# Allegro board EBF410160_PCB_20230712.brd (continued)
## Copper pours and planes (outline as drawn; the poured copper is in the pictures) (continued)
N18173560 on BOTTOM: 22.35,88.9 22.35,83.44 22.73,83.06 23.37,83.06 23.62,83.31 23.62,87.12 23.75,87.25 27.05,87.25 27.05,88.01 23.75,88.01 23.62,88.14 23.62,89.15 23.5,89.28 22.73,89.28

Small or netless copper shapes (teardrops, artwork), in the pictures only: 30 on TOP, 48 on BOTTOM

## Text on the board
Ref Des/Silkscreen Bottom: T1 | GND | R1 | T2 | EBF410160 | 20230712 | R2 | 2A | 2B | 1A | 1B | 3V3 | INT | RES | SCL | SDA | SCL0 | SDA0 | SCL1 | SDA1 | TXD0 | RXD0 | TXD1 | RXD1 | SIM CARD | TF CARD | MIPI CSI RX0 | MIPI CSI RX1
User.Comments: CR_DCDC2_2
Ref Des/Silkscreen Top: 12V | GND | 3V3 | 5V | DC-12V | RTC | RS232 | FAN | TYPE-C OTG | SPK | EAR | RS485 | MIC | HDMI2.0 PORT | ETH | I2C0 | SPI_D0 | USB3.0 HOST/OTG | I2C1 | UART0 | USB2.0 HOST | UART1 | IR_REC | SARADC | POWERON | RESET | RECOVERY | RXD | TXD | NC | INP | INN | EDP TOUCH | MIPI_DSI_TX1 | EDP DSI | LVDS TX0 | EBF410160 | 20230712 | + | -
COMPVAL_TYPE_BOTTOM: B | 12V | GND | 3V3 | 5V | 6 | A | T1_232 | 259 | DC-12V | RTC | R1_232 | T2_232 | FAN | USB_OTG | R2_232 | SPK | 4 | 485_2A | EAR | 485_2B | 145 | 485_1A | 143 | 485_1B | MIC | HDMI | 1 | 2 | 10 | C | USB3.0/USB2.0 HOST | 20 | 30 | USB2.0 HOST | 40 | 39 | IR_REC | D | C60 | Z4 | J3 | F1 | J6 | J1 | D1 | C2 | C3 | J7 | C1 | J2 | C189 | C190 | J29 | C185 | C186 | R216 | C188 | Z7 | R220 | Z10 | J11 | R74 | C131 | R73 | D29 | D28 | D30 | D31 | Q11 | Q10 | Q9 | J30 | R162 | R169 | R170 | R166 | R176 | R173 | R188 | J24 | C109 | R127 | R128 | Q7 | R126 | R125 | D36 | D35 | C107 | C108 | U17 | CN1 | C153 | R187 | R199 | R198 | C150 | R180 | C139 | R165 | R171 | U31 | C165 | R196 | R192 | C157 | C156 | R189 | Y2 | C167 | J18 | J19 | J22 | SARADC | PWRON | RESET | RECOVERY | RXD | TXD | NC | 260 | J12 | 146 | 144 | EDP TOUCH | ETH0 | MIPI_DSI_TX0 | MIPI_DSI_TX1 | EDP DSI | Z1 | R23 | SW4 | SW1 | SW2 | SW3 | C61 | R25 | C37 | R24 | J8 | R16 | LED4 | J16 | L8 | J25 | R215 | J27 | J26 | U27 | U28 | U26 | D27 | R190 | R191 | J14 | J10 | J23 | R160 | R158 | C144 | C137 | C154 | C145 | C138 | C155 | J15 | C180 | C179 | C184 | C110 | C111 | R214 | R213 | J17 | C106 | C181 | R212 | R211 | C183 | R194 | Q13 | LED3 | J13 | U29 | U33 | U32 | C136 | U30 | U34 | Q12 | LED2 | R146 | R49 | C119 | R145 | R48 | Q14 | C166 | R45 | R142 | C120 | U22 | R143 | U11 | LED1
DEVICE_TYPE_TOP: F | E | SPI_D0 | GND | C33 | C7 | L1 | R2 | R34 | R32 | R41 | Z3 | Z2 | R40 | U12 | R6 | R4 | C8 | C15 | Q3 | C21 | C22 | C23 | L3 | D7 | C67 | C19 | C36 | C35 | C34 | R26 | R33 | C41 | R31 | R13 | R11 | C20 | R1 | C4 | U25 | C126 | C125 | R153 | C124 | R150 | C58 | R38 | U2 | R12 | C10 | C11 | D2 | C38 | R27 | R30 | R29 | C51 | C50 | C26 | C25 | C24 | Q1 | Z8 | D34 | R138 | C31 | C32 | C13 | C12 | C14 | C30 | Z9 | U8 | D33 | Z11 | J5 | Z13 | C55 | U13 | D24 | Z6 | R218 | C187 | D22 | U15 | C86 | D25 | D23 | C91 | L6 | Y1 | D21 | R119 | R120 | D32 | R107 | R106 | U14 | R100 | R102 | R101 | R154 | R155 | R99 | R97 | R96 | U35 | R104 | R103 | R105 | R94 | R93 | R95 | R159 | C103 | C104 | R90 | R91 | C80 | C79 | R92 | R89 | R157 | L7 | R156 | L5 | C85 | U18 | R136 | U19 | C182 | U36 | R148 | U24 | C54 | L10 | R66 | R65 | R64 | R63 | C73 | R62 | R61 | R60 | D18 | D17 | D16 | D15 | C74 | D14 | D13 | D12 | C175 | C173 | C174 | U20 | R201 | C178 | C116 | R144 | U38 | R172 | C130 | U21 | R46 | C129 | C127 | J9 | U37 | R167 | R161 | C118 | R141 | R47 | C66 | C65 | J21 | J20 | 3V3 | INT | RST | SCL | SDA | SIM CARD | TF CARD | MIPI CSI RX0 | MIPI CSI RX1 | 24 | U3 | R42 | U5 | C62 | C6 | C40 | C49 | C43 | U9 | C5 | U10 | R19 | C39 | C48 | C42 | R22 | C28 | R20 | R39 | C29 | C59 | R21 | L2 | R50 | R59 | U4 | U7 | U6 | U1 | Q5 | D11 | R51 | D6 | C47 | C52 | C9 | C57 | R3 | R5 | R58 | Q2 | D9 | R18 | Q4 | Q6 | R17 | R57 | R10 | D10 | R135 | R9 | R223 | R56 | D26 | R134 | D8 | R52 | R224 | R37 | R53 | R55 | C70 | C191 | R54 | R217 | C72 | C71 | C68 | C69 | R82 | R81 | R219 | D20 | R68 | R72 | R78 | R77 | C76 | R70 | C94 | R221 | R80 | U16 | C92 | R79 | R98 | C83 | R108 | D19 | R109 | C84 | L9 | R67 | R71 | R76 | R75 | C75 | R69 | C77 | R195 | C162 | L4 | R193 | C78 | C163 | R114 | C164 | R111 | R117 | R116 | R118 | C105 | R110 | R112 | R124 | C102 | R123 | C98 | C82 | C87 | C81 | C90 | R130 | R131 | R137 | R84 | C171 | C114 | R85 | C170 | C115 | R83 | C172 | C123 | R86 | R205 | C122 | R203 | C169 | R206 | C168 | R87 | R88 | C121 | R147 | R140 | R139 | R204 | R133 | R200 | R132 | C176 | C113 | R202 | C112 | R210 | C177 | C117 | R209 | R208 | R186 | C64 | R185 | R184 | R44 | R183 | R181 | R179 | R178 | R177 | R152 | C128 | 20230523 | EBF410090
DEVICE_TYPE_BOTTOM: MASKROM | SS3 | SS1 | C4 | C2 | SS4 | SS2 | J6 | J5 | J9
BODY_CENTER: 2 | 80 | 79 | R1 | C6 | C1 | J3 | J1 | J4 | J2 | C3
DIMENSION: Unit:mm | X4
User.9: FIGURE | SIZE | 12.0 | 19.685 | 21.654 | 25.591 | 27.559 | 33.465 | 35.43 | 39.37 | 47.244 | 72.047 | 78.74 | 125.98 | 166.142 | 23.622 | 25.59 | 35.433 | 40.0 | 43.307 | 62.992 | 78.701 | 125.984 | 127.953 | 47.24x23.62 | 66.902x19.701 | 66.93x23.62 | 70.902x15.701 | 78.74x39.37 | 94.488x94.488 | 106.299x35.429 | DRILL CHART: TOP to BOTTOM | ALL UNITS ARE IN MILS | PLATED | NON-PLATED | QTY | 1177 | 2 | 19 | 30 | 18 | 4 | 8 | 10 | 14 | 1 | 3
